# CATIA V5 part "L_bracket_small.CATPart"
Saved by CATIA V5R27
Part number: 47065T845_Silver Corner Bracket
Revision: ANY
Definition: UNKNOWN
Nomenclature: 47065T845_Silver Corner Bracket
Source: Unknown
Bounding box of the stored display mesh (mm): x 0 to 38.1, y 0 to 38.1, z -16.637 to 16.637
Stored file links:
  \\triton.meca.polymtl.ca\usagers\zaoue\profiles\Desktop\varm_ass\bearing assy\L_bracket_small.CATPart
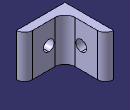
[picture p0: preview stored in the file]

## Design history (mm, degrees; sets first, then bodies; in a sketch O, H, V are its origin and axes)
Body1 "Cut-Extrude2" (main body)
  Solid1: solid without history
